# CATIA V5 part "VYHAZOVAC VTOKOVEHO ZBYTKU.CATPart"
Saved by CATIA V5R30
Part number: VYHAZOVAC VTOKOVEHO ZBYTKU
Bounding box of the stored display mesh (mm): x 0 to 146, y -6 to 6, z -6 to 6
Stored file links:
  C:\Users\ondra\Desktop\PŘÍLOHA P III\CATIA\VYHAZOVAC VTOKOVEHO ZBYTKU.CATPart
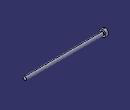
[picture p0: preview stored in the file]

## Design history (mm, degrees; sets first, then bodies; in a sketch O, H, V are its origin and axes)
Set1
  DatumSurface1 to DatumSurface9 "Z40/6x16"
  Plane1: type Offset, RefPlane yz-plane, Offset 146
  Join1: Elements (DatumSurface1; DatumSurface2; DatumSurface3; DatumSurface4; DatumSurface5; DatumSurface6; DatumSurface7; DatumSurface8; DatumSurface9)
Body1 (main body)
  CloseSurface1: CloseElement Join1
  Sketch1 on Plane1, origin (146, 0, 0), H (0, 1, 0), V (0, 0, 1)
    circle A1 centre (0, 0) radius 3
    radius A1 = 3
  Pocket1: profile Sketch1, direction (1, 0, 0), through (limit type 6)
